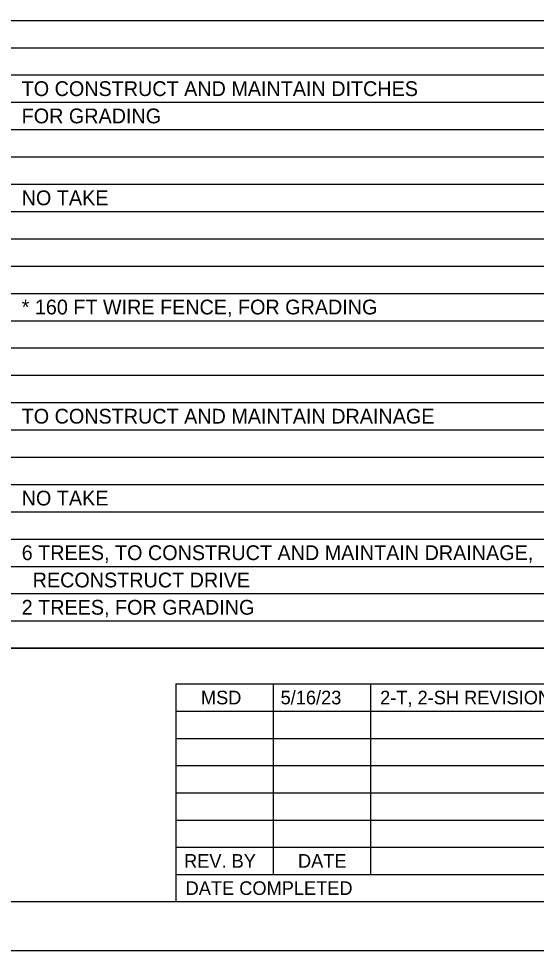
# Model space of a CAD drawing. Extents: x 0 to 34, y 0 to 22.
# Drawn here: x 23.58 to 28.9, y 0 to 9.58 of the extents above; entities that cross this region are included whole.
import ezdxf

# ---------------------------------------------------------------- set-up
doc = ezdxf.new("R2010")
doc.units = 0
for name, color, linetype in [('SH_Border', 7, 'Continuous'), ('SH_Cut_Line', 7, 'Continuous'), ('SH_Text', 7, 'Continuous')]:
    doc.layers.add(name, color=color, linetype=linetype)

msp = doc.modelspace()

# ---------------------------------------------------------------- linework, layer by layer
at = {"layer": 'SH_Border'}
msp.add_lwpolyline([(1.5, 21.5), (33.5, 21.5), (33.5, 0.5), (1.5, 0.5)], close=True, dxfattribs=at)
at = {"layer": 'SH_Cut_Line'}
msp.add_lwpolyline([(0, 0), (34, 0), (34, 22), (0, 22)], close=True, dxfattribs=at)
at = {"layer": 'SH_Text'}
for p, q in [((1.5, 9.5636), (32, 9.5636)), ((1.5, 9.2829), (32, 9.2829)), ((1.5, 9.0022), (32, 9.0022)), ((1.5, 8.7214), (32, 8.7214)), ((1.5, 8.4407), (32, 8.4407)), ((1.5, 8.16), (32, 8.16)), ((1.5, 7.8793), (32, 7.8793)), ((1.5, 7.5985), (32, 7.5985)), ((1.5, 7.3178), (32, 7.3178)), ((1.5, 7.0371), (32, 7.0371)), ((1.5, 6.7564), (32, 6.7564)), ((1.5, 6.4756), (32, 6.4756)), ((1.5, 6.1949), (32, 6.1949)), ((1.5, 5.9142), (32, 5.9142)), ((1.5, 5.6335), (32, 5.6335)), ((1.5, 5.3527), (32, 5.3527)), ((1.5, 5.072), (32, 5.072)), ((1.5, 4.7913), (32, 4.7913)), ((1.5, 4.5106), (32, 4.5106)), ((1.5, 4.2298), (32, 4.2298)), ((1.5, 3.9491), (32, 3.9491)), ((1.5, 3.6684), (32, 3.6684)), ((1.5, 3.3877), (32, 3.3877)), ((32, 3.1069), (1.5, 3.1069)), ((1.5, 3.1069), (32, 3.1069)), ((25.1966, 2.74), (25.1966, 0.5)), ((25.1966, 2.74), (32, 2.74)), ((26.1966, 2.74), (26.1966, 0.78)), ((27.1966, 2.74), (27.1966, 0.78)), ((25.1966, 2.46), (32, 2.46)), ((25.1966, 2.18), (32, 2.18)), ((25.1966, 1.9), (32, 1.9)), ((25.1966, 1.62), (32, 1.62)), ((25.1966, 1.34), (32, 1.34)), ((25.1966, 1.06), (32, 1.06)), ((25.1966, 0.78), (32, 0.78))]:
    msp.add_line(p, q, dxfattribs=at)

# ---------------------------------------------------------------- texts
for s, height, p in [('TO CONSTRUCT AND MAINTAIN DITCHES', 0.151922, (23.6113, 8.7858)), ('FOR GRADING', 0.151922, (23.6113, 8.5051)), ('NO TAKE', 0.15192, (23.6113, 7.6629)), ('* 160 FT WIRE FENCE, FOR GRADING', 0.151922, (23.6113, 6.54)), ('TO CONSTRUCT AND MAINTAIN DRAINAGE', 0.151922, (23.6113, 5.4171)), ('NO TAKE', 0.15192, (23.6113, 4.575)), ('6 TREES, TO CONSTRUCT AND MAINTAIN DRAINAGE,', 0.151922, (23.6113, 4.0135)), ('  RECONSTRUCT DRIVE', 0.151922, (23.6113, 3.7328)), ('2 TREES, FOR GRADING', 0.151922, (23.6113, 3.4521)), ('MSD', 0.14, (25.4542, 2.53)), ('5/16/23', 0.14, (26.2731, 2.53)), ('2-T, 2-SH REVISIONS, FROM NEGOTIATIONS', 0.14, (27.2966, 2.53)), ('REV. BY', 0.14, (25.2808, 0.85)), ('DATE', 0.14, (26.4521, 0.85)), ('DATE COMPLETED', 0.14, (25.2966, 0.57))]:
    msp.add_text(s, height=height, dxfattribs=at).set_placement(p)

doc.saveas('drawing.dxf')
